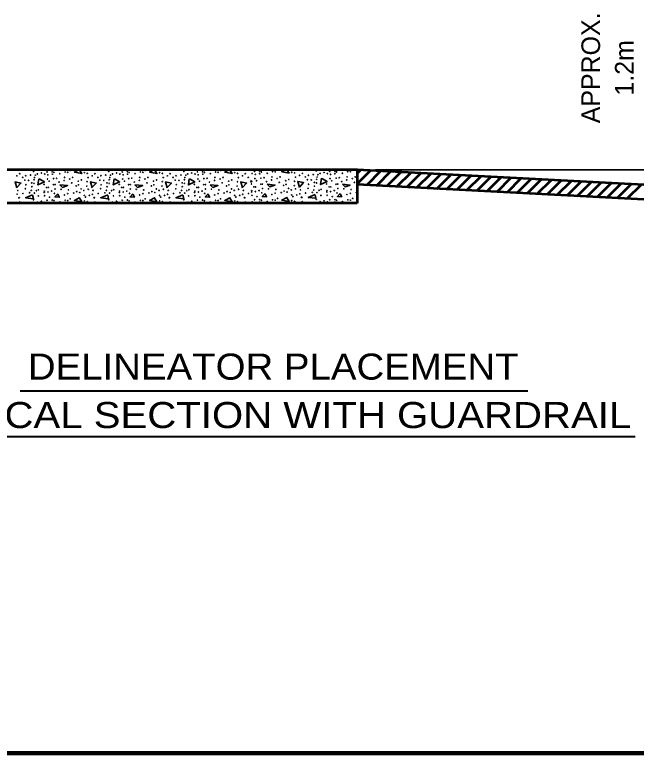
# Model space of a CAD drawing. Extents: x -89 to 766, y -60 to 484.
# Drawn here: x 57.5 to 157.5, y -48 to 70.9 of the extents above; entities that cross this region are included whole.
import ezdxf
from ezdxf.enums import TextEntityAlignment as Align

# ---------------------------------------------------------------- set-up
doc = ezdxf.new("R2010")
doc.units = 0
doc.header["$LTSCALE"] = 1.1
doc.layers.add('1', color=7, linetype='Continuous', lineweight=35)

msp = doc.modelspace()

# ---------------------------------------------------------------- linework, layer by layer
at = {"layer": '1', "lineweight": 53}
for p, q in [((112.579, 45.97), (168.776, 43.041)), ((112.579, 45.349), (113.169, 45.939)), ((112.579, 43.652), (114.782, 45.855)), ((114.104, 43.48), (116.395, 45.771)), ((115.716, 43.395), (118.008, 45.687)), ((117.329, 43.311), (119.621, 45.603)), ((118.941, 43.226), (121.234, 45.519)), ((120.554, 43.142), (122.847, 45.435)), ((122.166, 43.057), (124.46, 45.351)), ((123.779, 42.973), (126.073, 45.267)), ((125.391, 42.888), (127.686, 45.183)), ((127.004, 42.804), (129.299, 45.098)), ((128.617, 42.719), (130.911, 45.014)), ((130.229, 42.635), (132.524, 44.93)), ((131.842, 42.55), (134.137, 44.846)), ((133.454, 42.466), (135.75, 44.762)), ((135.067, 42.381), (137.363, 44.678)), ((136.679, 42.297), (138.976, 44.594)), ((138.292, 42.212), (140.589, 44.51)), ((139.904, 42.128), (142.202, 44.426)), ((141.517, 42.043), (143.815, 44.342)), ((143.129, 41.959), (145.428, 44.258)), ((144.742, 41.874), (147.041, 44.174)), ((146.355, 41.79), (148.654, 44.089)), ((147.967, 41.705), (150.267, 44.005)), ((168.776, 40.615), (112.579, 43.56)), ((149.58, 41.621), (151.88, 43.921)), ((151.192, 41.536), (153.493, 43.837)), ((152.805, 41.452), (155.106, 43.753)), ((154.417, 41.367), (156.719, 43.669)), ((156.03, 41.283), (158.332, 43.585)), ((112.579, 40.57), (-1.421, 40.57))]:
    msp.add_line(p, q, dxfattribs=at)
at = {"layer": '1'}
msp.add_line((115.532, 45.918), (160.612, 45.918), dxfattribs=at)
at = {"layer": '1', "lineweight": 40}
for p, q in [((58.353, 10.341), (140.025, 10.341)), ((41.13, 3.01), (157.278, 3.01))]:
    msp.add_line(p, q, dxfattribs=at)
at = {"layer": '1', "lineweight": 158}
msp.add_line((759.817, -48.017), (-31.783, -48.017), dxfattribs=at)
at = {"layer": '1', "lineweight": 53}
msp.add_lwpolyline([(-1.421, 45.97), (112.579, 45.97), (112.579, 43.567), (112.579, 40.57)], dxfattribs=at)
at = {"layer": '1'}
for points in [[(59.337, 45.97), (60.47, 45.839), (60.442, 45.97)], [(71.433, 45.97), (72.566, 45.839), (72.538, 45.97)], [(83.529, 45.97), (84.662, 45.839), (84.634, 45.97)], [(104.805, 46.044), (105.939, 45.913), (105.91, 46.044)], [(61.406, 44.471), (62.246, 43.991), (61.214, 43.487), (61.358, 44.495)], [(73.502, 44.471), (74.342, 43.991), (73.31, 43.487), (73.454, 44.495)], [(85.598, 44.471), (86.438, 43.991), (85.406, 43.487), (85.55, 44.495)], [(95.386, 44.198), (95.619, 44.065), (95.386, 43.952)], [(103.299, 43.105), (103.011, 44.065), (103.947, 43.873), (103.275, 43.153)], [(106.875, 44.545), (107.715, 44.065), (106.683, 43.561), (106.827, 44.569)], [(57.83, 43.031), (57.542, 43.991), (58.478, 43.799), (57.806, 43.079)], [(69.926, 43.031), (69.638, 43.991), (70.574, 43.799), (69.902, 43.079)], [(82.022, 43.031), (81.734, 43.991), (82.67, 43.799), (81.998, 43.079)], [(94.118, 43.031), (93.83, 43.991), (94.766, 43.799), (94.094, 43.079)], [(60.35, 41.879), (59.222, 41.423), (60.47, 41.279), (60.35, 41.831)], [(64.382, 42.047), (63.926, 41.567), (64.622, 41.519), (64.382, 41.999)], [(72.446, 41.879), (71.318, 41.423), (72.566, 41.279), (72.446, 41.831)], [(76.478, 42.047), (76.022, 41.567), (76.718, 41.519), (76.478, 41.999)], [(84.542, 41.879), (83.414, 41.423), (84.662, 41.279), (84.542, 41.831)], [(88.574, 42.047), (88.118, 41.567), (88.814, 41.519), (88.574, 41.999)], [(97.755, 42.121), (97.299, 41.641), (97.995, 41.593), (97.755, 42.073)], [(105.819, 41.953), (104.691, 41.497), (105.939, 41.353), (105.819, 41.905)], [(109.851, 42.121), (109.395, 41.641), (110.091, 41.593), (109.851, 42.073)], [(67.862, 41.423), (67.07, 40.991), (68.246, 40.775), (67.814, 41.447)], [(79.958, 41.423), (79.166, 40.991), (80.342, 40.775), (79.91, 41.447)], [(92.054, 41.423), (91.262, 40.991), (92.438, 40.775), (92.006, 41.447)], [(101.235, 41.497), (100.443, 41.065), (101.619, 40.849), (101.187, 41.521)]]:
    msp.add_lwpolyline(points, dxfattribs=at)
for points in [[(67.838, 45.97), (67.07, 45.551), (68.246, 45.335)], [(79.934, 45.97), (79.166, 45.551), (80.342, 45.335)], [(92.03, 45.97), (91.262, 45.551), (92.438, 45.335)], [(101.211, 46.044), (100.443, 45.625), (101.619, 45.409)], [(64.718, 43.535), (65.966, 43.391), (65.15, 43.103)], [(76.814, 43.535), (78.062, 43.391), (77.246, 43.103)], [(88.91, 43.535), (90.158, 43.391), (89.342, 43.103)], [(98.091, 43.609), (99.339, 43.465), (98.523, 43.177)], [(110.187, 43.609), (111.435, 43.465), (110.619, 43.177)]]:
    msp.add_lwpolyline(points, close=True, dxfattribs=at)
for centre in [(58.277, 45.292), (60.504, 45.673), (61.124, 45.276), (61.76, 45.419), (62.301, 45.244), (62.683, 45.594), (63.51, 45.61), (63.526, 45.228), (63.789, 45.514), (64.728, 45.308), (65.586, 45.578), (66, 45.53), (66.382, 45.817), (68.672, 45.467), (69.133, 45.355), (70.373, 45.292), (72.6, 45.673), (73.22, 45.276), (73.856, 45.419), (74.397, 45.244), (74.779, 45.594), (75.606, 45.61), (75.622, 45.228), (75.885, 45.514), (76.824, 45.308), (77.682, 45.578), (78.096, 45.53), (78.478, 45.817), (80.768, 45.467), (81.229, 45.355), (82.469, 45.292), (84.696, 45.673), (85.316, 45.276), (85.952, 45.419), (86.493, 45.244), (86.875, 45.594), (87.702, 45.61), (87.718, 45.228), (87.981, 45.514), (88.92, 45.308), (89.778, 45.578), (90.192, 45.53), (90.574, 45.817), (92.864, 45.467), (93.325, 45.355), (94.565, 45.292), (95.674, 45.318), (96.055, 45.668), (96.183, 45.191), (96.882, 45.684), (96.898, 45.302), (97.162, 45.589), (98.1, 45.382), (98.959, 45.652), (99.373, 45.605), (99.754, 45.891), (102.044, 45.541), (102.506, 45.43), (103.746, 45.366), (105.495, 45.159), (105.973, 45.748), (106.593, 45.35), (107.229, 45.493), (107.77, 45.318), (108.151, 45.668), (108.279, 45.191), (108.978, 45.684), (108.994, 45.302), (109.258, 45.589), (110.196, 45.382), (111.055, 45.652), (111.469, 45.605), (111.85, 45.891), (57.832, 44.958), (58.755, 44.703), (59.089, 44.258), (59.248, 44.974), (59.709, 44.226), (60.027, 45.085), (60.583, 44.321), (60.663, 44.687), (60.79, 45.069), (62.746, 44.449), (62.81, 45.117), (63.017, 44.098), (63.717, 44.512), (64.219, 44.576), (65.427, 44.226), (65.491, 44.703), (66.318, 44.449), (66.795, 44.703), (67.702, 44.098), (68.195, 44.305), (69.117, 44.019), (69.276, 44.671), (69.928, 44.958), (70.851, 44.703), (71.185, 44.258), (71.344, 44.974), (71.805, 44.226), (72.123, 45.085), (72.679, 44.321), (72.759, 44.687), (72.886, 45.069), (74.842, 44.449), (74.906, 45.117), (75.113, 44.098), (75.813, 44.512), (76.315, 44.576), (77.523, 44.226), (77.587, 44.703), (78.414, 44.449), (78.891, 44.703), (79.798, 44.098), (80.291, 44.305), (81.213, 44.019), (81.372, 44.671), (82.024, 44.958), (82.947, 44.703), (83.281, 44.258), (83.44, 44.974), (83.901, 44.226), (84.219, 45.085), (84.775, 44.321), (84.855, 44.687), (84.982, 45.069), (86.938, 44.449), (87.002, 45.117), (87.209, 44.098), (87.909, 44.512), (88.411, 44.576), (89.619, 44.226), (89.683, 44.703), (90.51, 44.449), (90.987, 44.703), (91.894, 44.098), (92.387, 44.305), (93.309, 44.019), (93.468, 44.671), (94.12, 44.958), (95.043, 44.703), (96.119, 44.523), (96.389, 44.173), (97.089, 44.586), (97.591, 44.65), (97.989, 44.03), (98.8, 44.3), (98.864, 44.777), (99.691, 44.523), (100.168, 44.777), (101.074, 44.173), (101.567, 44.38), (102.49, 44.093), (102.649, 44.746), (103.301, 45.032), (104.223, 44.777), (104.557, 44.332), (104.716, 45.048), (105.177, 44.3), (106.052, 44.396), (106.132, 44.761), (106.259, 45.143), (108.215, 44.523), (108.485, 44.173), (109.185, 44.586), (109.687, 44.65), (110.085, 44.03), (110.896, 44.3), (110.96, 44.777), (111.787, 44.523), (112.264, 44.777), (59.2, 42.874), (59.279, 43.526), (60.218, 43.828), (60.234, 43.208), (60.568, 43.749), (62.19, 43.574), (62.587, 43.096), (62.858, 43.096), (63.693, 43.539), (63.964, 43.558), (63.964, 42.842), (64.616, 43.955), (64.934, 42.794), (66.652, 43.828), (67.368, 43.335), (67.749, 43.51), (68.163, 42.858), (69.069, 43.303), (69.292, 42.794), (71.296, 42.874), (71.375, 43.526), (72.314, 43.828), (72.33, 43.208), (72.664, 43.749), (74.286, 43.574), (74.683, 43.096), (74.954, 43.096), (75.789, 43.539), (76.06, 43.558), (76.06, 42.842), (76.712, 43.955), (77.03, 42.794), (78.748, 43.828), (79.464, 43.335), (79.845, 43.51), (80.259, 42.858), (81.165, 43.303), (81.388, 42.794), (83.392, 42.874), (83.471, 43.526), (84.41, 43.828), (84.426, 43.208), (84.76, 43.749), (86.382, 43.574), (86.779, 43.096), (87.05, 43.096), (87.885, 43.539), (88.156, 43.558), (88.156, 42.842), (88.808, 43.955), (89.126, 42.794), (90.844, 43.828), (91.56, 43.335), (91.941, 43.51), (92.355, 42.858), (93.261, 43.303), (93.484, 42.794), (95.562, 43.648), (95.96, 43.171), (96.23, 43.171), (97.065, 43.613), (97.337, 43.632), (97.337, 42.916), (98.307, 42.868), (100.025, 43.902), (100.74, 43.409), (101.122, 43.584), (101.535, 42.932), (102.442, 43.377), (102.665, 42.868), (104.668, 42.948), (104.748, 43.6), (105.686, 43.902), (105.702, 43.282), (106.036, 43.823), (106.768, 42.789), (107.658, 43.648), (108.056, 43.171), (108.326, 43.171), (109.161, 43.613), (109.433, 43.632), (109.433, 42.916), (110.403, 42.868), (112.121, 43.902), (57.864, 41.989), (57.975, 42.619), (58.802, 42.116), (59.868, 42.227), (60.122, 42.603), (60.631, 42.179), (60.965, 42.571), (61.267, 41.734), (61.299, 42.714), (62.222, 42.291), (62.238, 42.492), (62.269, 41.75), (62.826, 42.354), (63.414, 42.508), (63.853, 42.132), (65.459, 41.877), (66, 42.084), (66.127, 42.699), (66.97, 42.195), (67.447, 42.428), (67.924, 42.275), (68.592, 42.619), (68.672, 41.798), (69.483, 41.798), (69.96, 41.989), (70.071, 42.619), (70.898, 42.116), (71.964, 42.227), (72.218, 42.603), (72.727, 42.179), (73.061, 42.571), (73.363, 41.734), (73.395, 42.714), (74.318, 42.291), (74.334, 42.492), (74.365, 41.75), (74.922, 42.354), (75.51, 42.508), (75.949, 42.132), (77.555, 41.877), (78.096, 42.084), (78.223, 42.699), (79.066, 42.195), (79.543, 42.428), (80.02, 42.275), (80.688, 42.619), (80.768, 41.798), (81.579, 41.798), (82.056, 41.989), (82.167, 42.619), (82.994, 42.116), (84.06, 42.227), (84.314, 42.603), (84.823, 42.179), (85.157, 42.571), (85.459, 41.734), (85.491, 42.714), (86.414, 42.291), (86.43, 42.492), (86.461, 41.75), (87.018, 42.354), (87.606, 42.508), (88.045, 42.132), (89.651, 41.877), (90.192, 42.084), (90.319, 42.699), (91.162, 42.195), (91.639, 42.428), (92.116, 42.275), (92.784, 42.619), (92.864, 41.798), (93.675, 41.798), (94.152, 41.989), (94.263, 42.619), (95.09, 42.116), (95.594, 42.365), (95.61, 42.566), (95.642, 41.824), (96.198, 42.429), (96.453, 41.601), (96.787, 42.582), (97.226, 42.206), (98.832, 41.951), (99.373, 42.158), (99.5, 42.773), (100.343, 42.27), (100.82, 42.502), (101.297, 42.349), (101.965, 42.693), (102.044, 41.872), (102.235, 41.617), (102.855, 41.872), (103.333, 42.063), (103.444, 42.693), (104.271, 42.19), (105.336, 42.301), (105.591, 42.677), (106.1, 42.254), (106.434, 42.646), (106.736, 41.808), (107.69, 42.365), (107.706, 42.566), (107.738, 41.824), (108.294, 42.429), (108.549, 41.601), (108.883, 42.582), (109.322, 42.206), (110.928, 41.951), (111.469, 42.158), (111.596, 42.773), (112.439, 42.27), (58.134, 41.432), (58.198, 41.432), (58.277, 40.732), (60.504, 41.113), (61.124, 40.716), (61.76, 40.859), (62.301, 40.684), (62.683, 41.034), (63.08, 41.527), (63.51, 41.05), (63.526, 40.668), (63.789, 40.954), (64.728, 40.748), (65.586, 41.018), (66, 40.97), (66.382, 41.257), (68.672, 40.907), (68.863, 41.543), (69.133, 40.795), (70.23, 41.432), (70.294, 41.432), (70.373, 40.732), (72.6, 41.113), (73.22, 40.716), (73.856, 40.859), (74.397, 40.684), (74.779, 41.034), (75.176, 41.527), (75.606, 41.05), (75.622, 40.668), (75.885, 40.954), (76.824, 40.748), (77.682, 41.018), (78.096, 40.97), (78.478, 41.257), (80.768, 40.907), (80.959, 41.543), (81.229, 40.795), (82.326, 41.432), (82.39, 41.432), (82.469, 40.732), (84.696, 41.113), (85.316, 40.716), (85.952, 40.859), (86.493, 40.684), (86.875, 41.034), (87.272, 41.527), (87.702, 41.05), (87.718, 40.668), (87.981, 40.954), (88.92, 40.748), (89.778, 41.018), (90.192, 40.97), (90.574, 41.257), (92.864, 40.907), (93.055, 41.543), (93.325, 40.795), (94.422, 41.432), (94.486, 41.432), (94.565, 40.732), (95.674, 40.758), (96.055, 41.108), (96.882, 41.124), (96.898, 40.742), (97.162, 41.029), (98.1, 40.822), (98.959, 41.092), (99.373, 41.045), (99.754, 41.331), (102.044, 40.981), (102.506, 40.87), (103.603, 41.506), (103.667, 41.506), (103.746, 40.806), (105.973, 41.188), (106.593, 40.79), (107.229, 40.933), (107.77, 40.758), (108.151, 41.108), (108.978, 41.124), (108.994, 40.742), (109.258, 41.029), (110.196, 40.822), (111.055, 41.092), (111.469, 41.045), (111.85, 41.331)]:
    msp.add_circle(centre, 0.0318, dxfattribs=at)
for centre, start, end in [((58.134, 45.992), 223.38683, 316.61317), ((58.198, 45.992), 223.38683, 316.61317), ((70.23, 45.992), 223.38683, 316.61317), ((70.294, 45.992), 223.38683, 316.61317), ((82.326, 45.992), 223.38683, 316.61317), ((82.39, 45.992), 223.38683, 316.61317), ((94.422, 45.992), 223.38683, 316.61317), ((94.486, 45.992), 223.38683, 316.61317), ((103.603, 46.066), 223.38683, 316.61317), ((103.667, 46.066), 223.38683, 316.61317), ((62.81, 40.557), 24.63166, 155.36834), ((74.906, 40.557), 24.63166, 155.36834), ((87.002, 40.557), 24.63166, 155.36834), ((96.183, 40.631), 24.63166, 155.36834), ((108.279, 40.631), 24.63166, 155.36834)]:
    msp.add_arc(centre, 0.0318, start, end, dxfattribs=at)

# ---------------------------------------------------------------- texts
for s, p in [('APPROX.', (151.64, 62.344)), ('1.2m', (157.04, 62.344))]:
    msp.add_text(s, height=3, rotation=90, dxfattribs=at).set_placement(p, align=Align.CENTER)
for s, width, p in [('DELINEATOR PLACEMENT', 1.1, (99.063, 12.141)), ('TYPICAL SECTION WITH GUARDRAIL', 1.15, (99.063, 4.341))]:
    msp.add_text(s, height=4.2, dxfattribs=dict(at, width=width)).set_placement(p, align=Align.CENTER)

doc.saveas('drawing.dxf')
